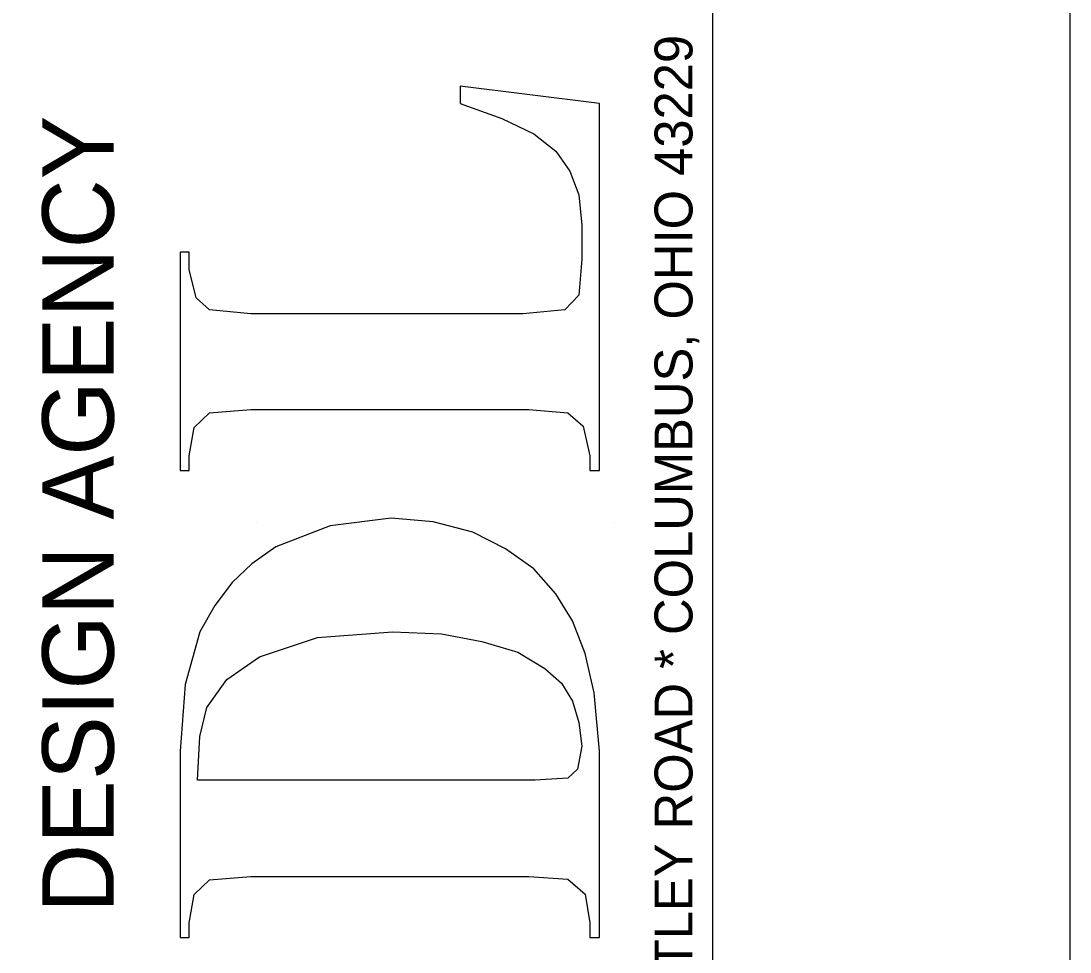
# Model space of a CAD drawing. Extents: x 0 to 34, y 0 to 22.
# Drawn here: x 32.533 to 34, y 18.9 to 20.202 of the extents above; entities that cross this region are included whole.
import ezdxf

# ---------------------------------------------------------------- set-up
doc = ezdxf.new("R2010")
doc.units = 0
for name, color, linetype in [('SH_Border', 7, 'Continuous'), ('SH_Cut_Line', 7, 'Continuous'), ('SH_Data', 7, 'Continuous')]:
    doc.layers.add(name, color=color, linetype=linetype)

msp = doc.modelspace()

# ---------------------------------------------------------------- linework, layer by layer
at = {"layer": 'SH_Border'}
msp.add_lwpolyline([(2, 21.5), (33.5, 21.5), (33.5, 0.5), (2, 0.5)], close=True, dxfattribs=at)
at = {"layer": 'SH_Cut_Line'}
msp.add_lwpolyline([(0, 0), (34, 0), (34, 22), (0, 22)], close=True, dxfattribs=at)
at = {"layer": 'SH_Data'}
for p, q in [((32.8625, 19.5), (32.8625, 19.5)), ((33.1125, 19.5), (33.1125, 19.5)), ((33.3625, 19.5), (33.3625, 19.5))]:
    msp.add_line(p, q, dxfattribs=at)
for points in [[(33.1468, 20.1103), (33.1468, 20.0861), (33.2052, 20.0654), (33.2501, 20.0439), (33.2806, 20.0196), (33.3004, 19.9917), (33.3129, 19.9585), (33.3174, 19.9163), (33.3174, 19.8687), (33.3129, 19.8184), (33.2932, 19.7977), (33.2348, 19.7924), (32.854, 19.7924), (32.7966, 19.7977), (32.7777, 19.8148), (32.7678, 19.8543), (32.7678, 19.8786), (32.7552, 19.8786), (32.7552, 19.5732), (32.7678, 19.5732), (32.7678, 19.5939), (32.775, 19.6334), (32.7966, 19.654), (32.854, 19.6586), (33.2429, 19.6586), (33.2977, 19.654), (33.3192, 19.6352), (33.3282, 19.5939), (33.3282, 19.5732), (33.3417, 19.5732), (33.3417, 20.0861)], [(33.3417, 18.9203), (33.3417, 19.1808), (33.3345, 19.2624), (33.3219, 19.3173), (33.304, 19.363), (33.2806, 19.4007), (33.2501, 19.4358), (33.2106, 19.4636), (33.1647, 19.487), (33.1091, 19.5014), (33.0507, 19.5068), (32.9654, 19.496), (32.889, 19.4664), (32.8558, 19.443), (32.828, 19.4169), (32.8038, 19.3846), (32.7831, 19.3478), (32.7624, 19.2741), (32.7552, 19.1808), (32.7552, 18.9203), (32.7678, 18.9203), (32.7678, 18.9409), (32.775, 18.9804), (32.7966, 19.0011), (32.854, 19.0056), (33.2429, 19.0056), (33.2977, 19.002), (33.3219, 18.9813), (33.3282, 18.9409), (33.3282, 18.9203)], [(32.7795, 19.1403), (32.7831, 19.2014), (32.7929, 19.2418), (32.8208, 19.2813), (32.8665, 19.3128), (32.9474, 19.3397), (33.0525, 19.3478), (33.1208, 19.3451), (33.1773, 19.3343), (33.2276, 19.3191), (33.2654, 19.2966), (33.2887, 19.2759), (33.304, 19.2508), (33.3129, 19.2211), (33.3174, 19.188), (33.3111, 19.1556), (33.2977, 19.143), (33.2519, 19.1403)]]:
    msp.add_lwpolyline(points, close=True, dxfattribs=at)

# ---------------------------------------------------------------- texts
for s, height, p in [('6121 HUNTLEY ROAD * COLUMBUS, OHIO 43229', 0.052988, (33.4719, 18.5439)), ('DESIGN AGENCY', 0.1, (32.6625, 18.9548))]:
    msp.add_text(s, height=height, rotation=90, dxfattribs=at).set_placement(p)

doc.saveas('drawing.dxf')
